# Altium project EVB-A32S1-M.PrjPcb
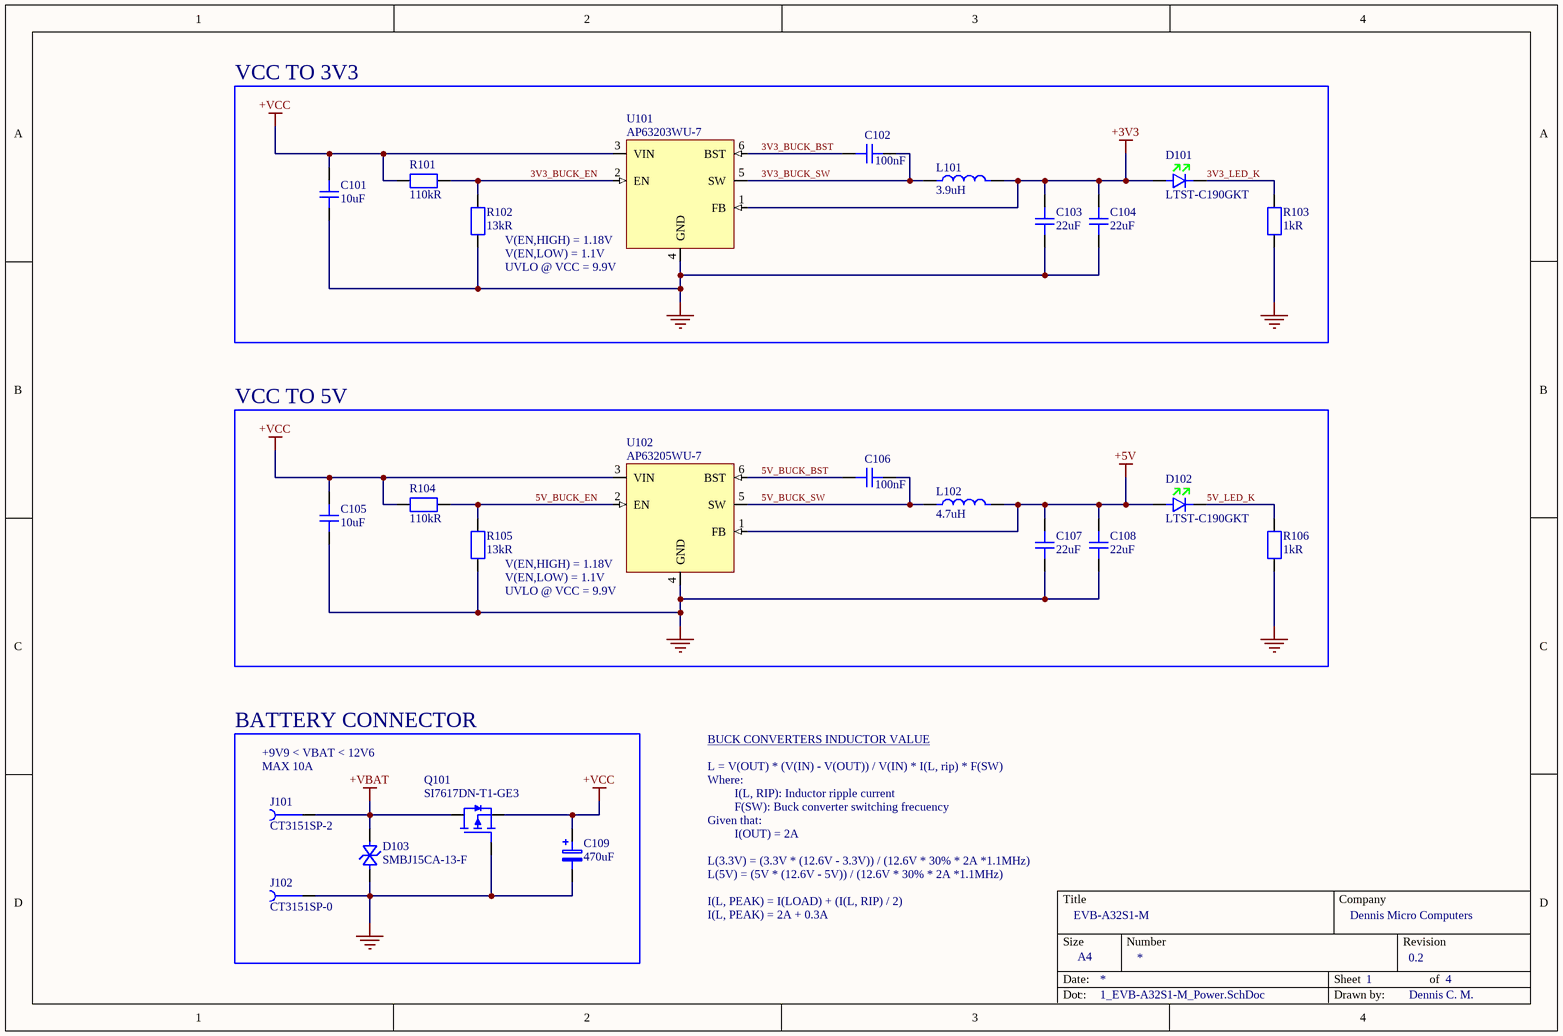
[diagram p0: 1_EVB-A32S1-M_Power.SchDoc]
CompanyName: Dennis Micro Computers; DrawnBy: Dennis C. M.; Revision: 0.2; Title: EVB-A32S1-M
4 sheets, 111 parts. Net scope: flat (ports and power ports of the same name join across sheets).
Board file: EVB-A32S1-M_PCB.PcbDoc
Sheets:
  1_EVB-A32S1-M_Power.SchDoc
  2_EVB-A32S1-M_MCU.SchDoc
  3_EVB-A32S1-M_Motor.SchDoc
  4_EVB-A32S1-M_Sensing.SchDoc

## Sheet 1_EVB-A32S1-M_Power.SchDoc: EVB-A32S1-M
size A4; SheetNumber: 1; SheetTotal: 4

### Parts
C101  value 10uF  [C_Samsung_CL_0805_A]  (hidden comment: CL21A106KOQNNNE)
C102  value 100nF  [C_Samsung_CL_0402_A]  (hidden comment: CL05B104KP5NNNC)
C103  value 22uF  [C_Yageo_CC_0805_A]  (hidden comment: CC0805MKX5R6BB226)
C104  value 22uF  [C_Yageo_CC_0805_A]  (hidden comment: CC0805MKX5R6BB226)
C105  value 10uF  [C_Samsung_CL_0805_A]  (hidden comment: CL21A106KOQNNNE)
C106  value 100nF  [C_Samsung_CL_0402_A]  (hidden comment: CL05B104KP5NNNC)
C107  value 22uF  [C_Yageo_CC_0805_A]  (hidden comment: CC0805MKX5R6BB226)
C108  value 22uF  [C_Yageo_CC_0805_A]  (hidden comment: CC0805MKX5R6BB226)
C109  value 470uF  [C_Rubycon_10x16mm_TH]  (hidden comment: 35ZLH470MEFC10X16)
D101  LTST-C190GKT  [D_LED_Lite-On_Green_0603_A]
D102  LTST-C190GKT  [D_LED_Lite-On_Green_0603_A]
D103  SMBJ15CA-13-F  [D_TVS_BI_Diodes_SMBJ15CA-13-F_A]
J101  CT3151SP-2  [J_CalTest_CT3151SP-2]
J102  CT3151SP-0  [J_CalTest_CT3151SP-0]
L101  value 3.9uH  [L_Murata_1255AY-XXXX=P3]  (hidden comment: 1255AY-3R9N=P3)
L102  value 4.7uH  [L_Murata_1255AY-XXXX=P3]  (hidden comment: 1255AY-4R7M=P3)
Q101  SI7617DN-T1-GE3  [Q_Vishay_PowerPACK-1212-8]
R101  value 110kR  [R_Yageo_RCL_0402_A]  (hidden comment: RC0402FR-07110KL)
R102  value 13kR  [R_Yageo_RCL_0402_A]  (hidden comment: RC0402FR-0713KL)
R103  value 1kR  [R_Yageo_RCL_0402_A]  (hidden comment: RC0402FR-071KL)
R104  value 110kR  [R_Yageo_RCL_0402_A]  (hidden comment: RC0402FR-07110KL)
R105  value 13kR  [R_Yageo_RCL_0402_A]  (hidden comment: RC0402FR-0713KL)
R106  value 1kR  [R_Yageo_RCL_0402_A]  (hidden comment: RC0402FR-071KL)
U101  AP63203WU-7  [U_Diodes_AP623xx]
U102  AP63205WU-7  [U_Diodes_AP623xx]

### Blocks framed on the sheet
VCC TO 3V3: C101-C104 D101 L101 R101-R103 U101
VCC TO 5V: C105-C108 D102 L102 R104-R106 U102
BATTERY CONNECTOR: C109 D103 J101 J102 Q101

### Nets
+3V3: C103.2 C104.2 D101.2 L101.2 U101.1(FB)
+5V: C107.2 C108.2 D102.2 L102.2 U102.1(FB)
+VBAT: D103.1 J101.1 Q101.1(D)
+VCC: C101.2 C105.2 C109.1 Q101.3(S) R101.2 R104.2 U101.3(VIN) U102.3(VIN)
GND: C101.1 C103.1 C104.1 C105.1 C107.1 C108.1 C109.2 D103.2 J102.1 Q101.2(G) R102.1 R103.1 R105.1 R106.1 U101.4(GND) U102.4(GND)
3V3_BUCK_BST: C102.2 U101.6(BST)
3V3_BUCK_EN: R101.1 R102.2 U101.2(EN)
3V3_BUCK_SW: C102.1 L101.1 U101.5(SW)
3V3_LED_K: D101.1 R103.2
5V_BUCK_BST: C106.2 U102.6(BST)
5V_BUCK_EN: R104.1 R105.2 U102.2(EN)
5V_BUCK_SW: C106.1 L102.1 U102.5(SW)
5V_LED_K: D102.1 R106.2

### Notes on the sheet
- (near U101) V(EN,HIGH) = 1.18V
- V(EN,LOW) = 1.1V
- (near U101) UVLO @ VCC = 9.9V
- (near U102) V(EN,HIGH) = 1.18V
- (near U102) UVLO @ VCC = 9.9V
- +9V9 < VBAT < 12V6
- (near J101) MAX 10A
- L = V(OUT) * (V(IN) - V(OUT)) / V(IN) * I(L, rip) * F(SW)
- BUCK CONVERTERS INDUCTOR VALUE
- Where:
- Given that:
- I(L, RIP): Inductor ripple current
- F(SW): Buck converter switching frecuency
- I(OUT) = 2A
- L(3.3V) = (3.3V * (12.6V - 3.3V)) / (12.6V * 30% * 2A *1.1MHz)
- L(5V) = (5V * (12.6V - 5V)) / (12.6V * 30% * 2A *1.1MHz)
- I(L, PEAK) = I(LOAD) + (I(L, RIP) / 2)
- I(L, PEAK) = 2A + 0.3A

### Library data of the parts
C101 C105 = CMP-001-00022-4: Multilayer Ceramic Capacitor, 10 uF, 16 V, ± 10%, X5R, 0805 [2012 Metric]; Voltage Rating (DC): 16V; Dielectric: X7R
C102 C106 = CMP-001-00023-3: Multilayer Ceramic Capacitor, 0.1 uF, 10 V, ± 10%, X7R, 0402 [1005 Metric]; Voltage Rating: 10V
C103 C104 C107 C108 = CMP-001-00014-8: Multilayer Ceramic Capacitor, 22 uF, 10 V, ± 20%, X5R, 0805 [2012 Metric]; Voltage Rating (DC): 10V
C109 = CMP-001-00025-5: Cap Aluminum 470uF 35V 20% (10 X 16mm) Radial 5mm 1760mA 10000h 105 C Bulk; Life (Hours): 10000Hour; Lead Diameter: 0.6mm; Leakage Current: 3uA; Dielectric Material: Aluminium; Ripple Current: 1.76A; Impedance: 28mR
D101 D102 = CMP-007-00001-3: LED Uni-Color Green 565nm 2-Pin Chip LED T/R; Forward Current: 30mA; Forward Voltage: 2.1V; Luminous Intensity: 6mcd; Lens Transparency: Clear; Power Dissipation: 100mW; Lens Style: Flat,Diffused,Colorless,Rectangular,Clear; Lens Size: 0.8mm; Reverse Voltage: 5V; Viewing Angle: 130°; Test Current: 10mA; Dominant Wavelength: 569nm; Lens Color: Colorless; Number of Elements: 1; Voltage: 2V
D103 = CMP-004-00000-11: Tvs Diode, Bidir, 15V, 600W, Do-214Aa Rohs Compliant: Yes; Max Reverse Leakage Current: 5uA; Reverse Breakdown Voltage: 16.7V; Breakdown Voltage: 19.2V; Clamping Voltage: 24.4V; Power Line Protection: No; Max Surge Current: 24A; Number of Bidirectional Channels: 1; Test Current: 1mA; Value: 280pF; Polarity: Bidirectional; Diode Type: ZENER
J101 = CMP-002-00001-14: Conn 4mm Safety Banana Jack F 1 POS Solder RA Thru-Hole 1 Port Bag; pin to pad: 1>1+2+3+4; Body Material: Nylon,Polyamide,PA66; Insulation: Mating End Insulated; Gender: Female
J102 = CMP-002-00000-17: Conn 4mm Safety Banana Jack F 1 POS Solder RA Thru-Hole 1 Port Bag; pin to pad: 1>1+2+3+4; Body Material: Nylon,Polyamide,PA66; Insulation: Mating End Insulated; Gender: Female
L101 = CMP-006-00002-7: Inductor Power Shielded Wirewound 3.9uH 30% 100KHz Ferrite 4.2A 0.0264Ohm DCR 2424 T/R; DC Resistance (DCR): 26.4mR; Saturation Current: 4.7A
L102 = CMP-006-00001-10: Inductor Power Shielded Wirewound 4.7uH 20% 100KHz Ferrite 4A 0.0276Ohm DCR 2424 T/R; DC Resistance (DCR): 27.6mR; Current Rating: 4.5A
Q101 = CMP-00000-19: P CHANNEL MOSFET, -30V, 35A; Transistor; Transistor Polarity: P Channel; Continuous Drain Current Id: -35A; Source; pin to pad: 1>5+6+7+8 2>4 3>1+2+3; Rise Time: 43ns; Drain to Source Resistance: 12.3mR; Turn-Off Delay Time: 30ns; Turn-On Delay Time: 40ns; Threshold Voltage: -2.5V; Max Power Dissipation: 52W; Fall Time: 11ns; Power Dissipation: 3.7W; Polarity: P-CHANNEL; Number of Elements: 1; Input Capacitance: 1.8nF; Gate to Source Voltage (Vgs): 25V
R101 R104 = CMP-009-00000-11: SMD Chip Resistor, 110 kOhm, ± 1%, 63 mW, 0402 [1005 Metric], Thick Film, General Purpose; Max Power Dissipation: 63mW; Voltage Rating (DC): 50V; Temperature Coefficient: 100ppm/°C
R102 R105 = CMP-009-00001-11: SMD Chip Resistor, 13 kOhm, ± 1%, 63 mW, 0402 [1005 Metric], Thick Film, General Purpose; Temperature Coefficient: 100ppm/°C; Voltage Rating: 50V; Max Power Dissipation: 63mW; Power Rating: 62.5mW
R103 R106 = CMP-009-00002-11: SMD Chip Resistor, 1 kOhm, ± 1%, 62.5 mW, 0402 [1005 Metric], Thick Film, General Purpose; Temperature Coefficient: 100ppm/°C; Voltage Rating (AC): 50V; Power Rating: 62.5mW; Max Power Dissipation: 63mW
U101 = CMP-019-00004-17: AP63203 Series 3.3 V 2 A SMT Fixed Low IQ Synchronous Buck - TSOT-26; Max Duty Cycle: 100%; Output Voltage: 3.3V; Number of Outputs: 1; Max Supply Voltage: 32V; Switching Frequency: 1.1MHz; Min Supply Voltage: 3.8V; Nominal Supply Current: 22uA; Output Current: 2A
U102 = CMP-019-00003-17: AP63205 Series 32 V 2 A 1.1 MHz Synchronous Buck Converter -TSOT-26; Number of Outputs: 1; Max Duty Cycle: 100%; Output Current: 2A; Switching Frequency: 1.1MHz; Max Supply Voltage: 32V; Output Voltage: 5V; Nominal Supply Current: 22uA; Min Supply Voltage: 3.8V

## Sheet 2_EVB-A32S1-M_MCU.SchDoc: EVB-A32S1-M
size A4; SheetNumber: 2; SheetTotal: 4
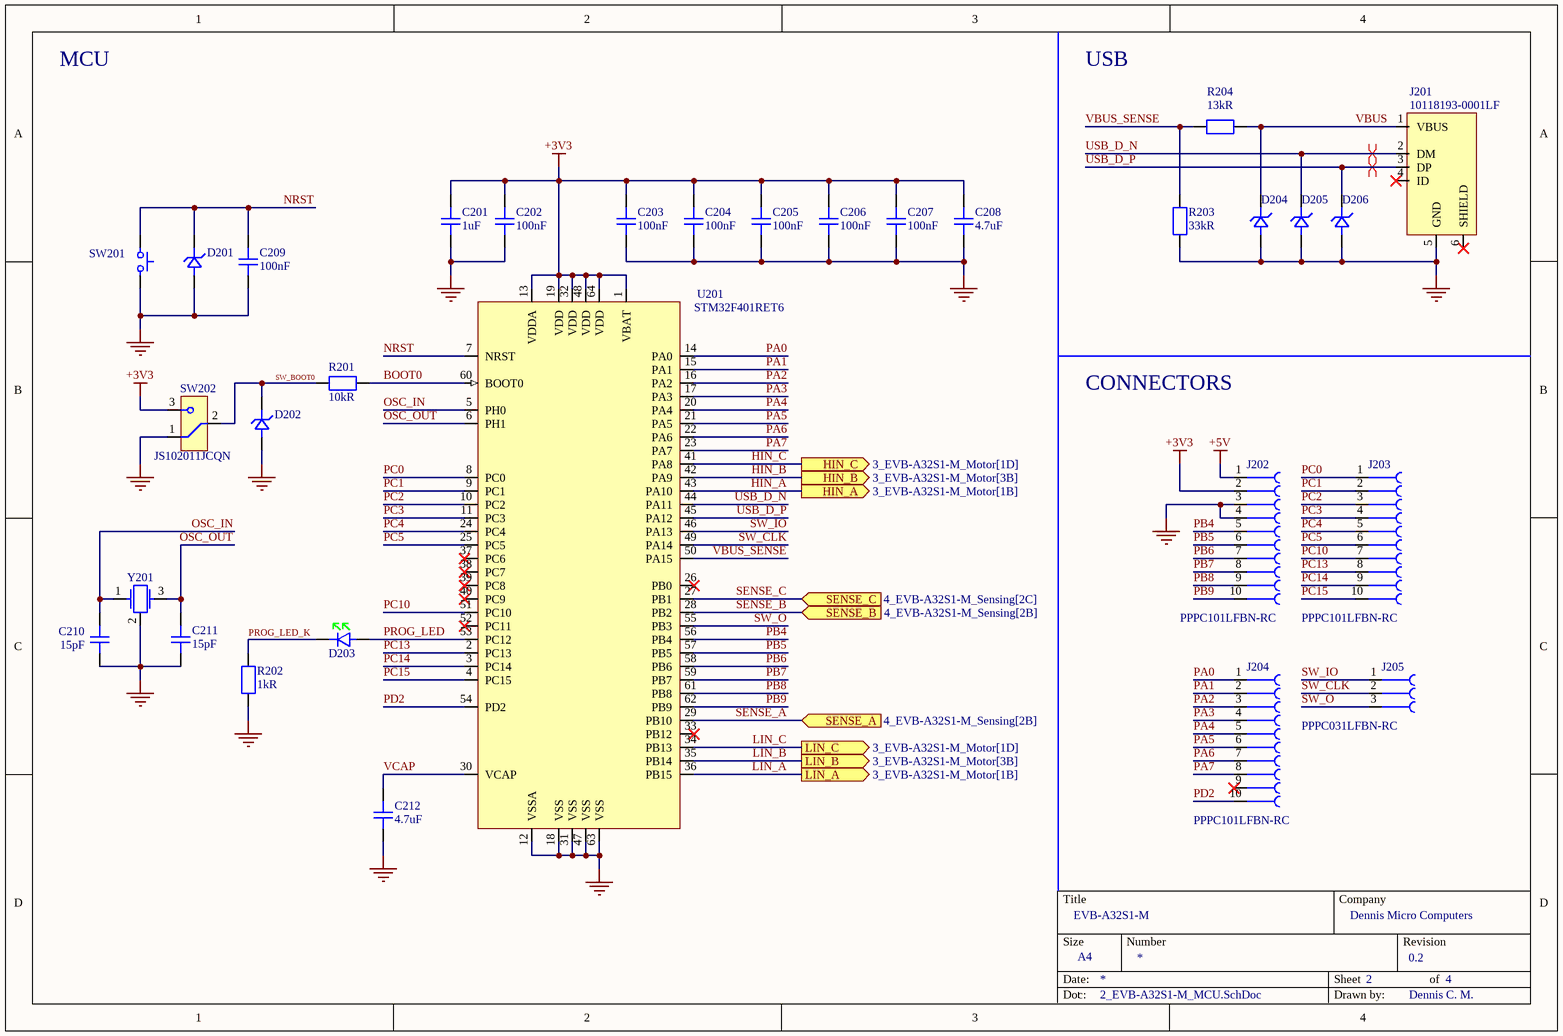
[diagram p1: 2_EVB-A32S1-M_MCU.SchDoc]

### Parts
C201  value 1uF  [C_Yageo_CC_0603_A]  (hidden comment: CC0603KRX7R7BB105)
C202  value 100nF  [C_Samsung_CL_0402_A]  (hidden comment: CL05B104KP5NNNC)
C203  value 100nF  [C_Samsung_CL_0402_A]  (hidden comment: CL05B104KP5NNNC)
C204  value 100nF  [C_Samsung_CL_0402_A]  (hidden comment: CL05B104KP5NNNC)
C205  value 100nF  [C_Samsung_CL_0402_A]  (hidden comment: CL05B104KP5NNNC)
C206  value 100nF  [C_Samsung_CL_0402_A]  (hidden comment: CL05B104KP5NNNC)
C207  value 100nF  [C_Samsung_CL_0402_A]  (hidden comment: CL05B104KP5NNNC)
C208  value 4.7uF  [C_Samsung_CL_0402_A]  (hidden comment: CL05A475MP5NRNC)
C209  value 100nF  [C_Samsung_CL_0402_A]  (hidden comment: CL05B104KP5NNNC)
C210  value 15pF  [C_Yageo_CC_0402_A]  (hidden comment: CC0402JRNPO9BN150)
C211  value 15pF  [C_Yageo_CC_0402_A]  (hidden comment: CC0402JRNPO9BN150)
C212  value 4.7uF  [C_Samsung_CL_0402_A]  (hidden comment: CL05A475MP5NRNC)
D201  D5V0F1U2S9-7  [D_TVS_Uni_Diodes_SOD-923_B]  (value not drawn)
D202  D5V0F1U2S9-7  [D_TVS_Uni_Diodes_SOD-923_B]  (value not drawn)
D203  LTST-C190GKT  [D_LED_Lite-On_Green_0603_A]  (value not drawn)
D204  D5V0F1U2S9-7  [D_TVS_Uni_Diodes_SOD-923_B]  (value not drawn)
D205  D5V0F1U2S9-7  [D_TVS_Uni_Diodes_SOD-923_B]  (value not drawn)
D206  D5V0F1U2S9-7  [D_TVS_Uni_Diodes_SOD-923_B]  (value not drawn)
J201  10118193-0001LF  [J_USB_Micro-B_Amphenol_10118193-0001LF]
J202  PPPC101LFBN-RC  [J_Sullins_01x07_Socket_2.54mm]
J203  PPPC101LFBN-RC  [J_Sullins_01x07_Socket_2.54mm]
J204  PPPC101LFBN-RC  [J_Sullins_01x07_Socket_2.54mm]
J205  PPPC031LFBN-RC  [J_Sullins_01x03_Socket_2.54mm]
R201  value 10kR  [R_Yageo_RCL_0402_A]  (hidden comment: RC0402FR-0710KL)
R202  value 1kR  [R_Yageo_RCL_0402_A]  (hidden comment: RC0402FR-071KL)
R203  value 33kR  [R_Yageo_RCL_0402_A]  (hidden comment: RC0402FR-0733KL)
R204  value 13kR  [R_Yageo_RCL_0402_A]  (hidden comment: RC0402FR-0713KL)
SW201  PTS647SN50SMTR2LFS  [SW_Tactitle_SPST_C&K_PTS647SN50SMTR2LFS]  (value not drawn)
SW202  JS102011JCQN  [SW_Slide_C&K_JS102011JCQN]
U201  STM32F401RET6  [U_ST_STM32F401xD/xE_B]
Y201  ECS-240-12-37B-CKY-TR  [Y_Crystal_GND24_ECS_240-12-37B-CKY-TR]  (value not drawn)

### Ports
HIN_A (out, see 3_EVB-A32S1-M_Motor[1B]), HIN_B (out, see 3_EVB-A32S1-M_Motor[3B]), HIN_C (out, see 3_EVB-A32S1-M_Motor[1D]), LIN_A (out, see 3_EVB-A32S1-M_Motor[1B]), LIN_B (out, see 3_EVB-A32S1-M_Motor[3B]), LIN_C (out, see 3_EVB-A32S1-M_Motor[1D]), SENSE_A (in, see 4_EVB-A32S1-M_Sensing[2B]), SENSE_B (in, see 4_EVB-A32S1-M_Sensing[2B]), SENSE_C (in, see 4_EVB-A32S1-M_Sensing[2C])

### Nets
+3V3: C201.2 C202.2 C203.2 C204.2 C205.2 C206.2 C207.2 C208.2 J202.2 SW202.3 U201.1(VBAT) U201.13(VDDA) U201.19(VDD) U201.32(VDD) U201.48(VDD) U201.64(VDD)
+5V: J202.1
GND: C201.1 C202.1 C203.1 C204.1 C205.1 C206.1 C207.1 C208.1 C209.1 C210.1 C211.1 C212.1 D201.2 D202.2 D204.2 D205.2 D206.2 J201.5(GND) J202.3 J202.4 R202.1 R203.1 SW201.2 SW202.1 U201.12(VSSA) U201.18(VSS) U201.31(VSS) U201.47(VSS) U201.63(VSS) Y201.2
BOOT0: R201.2 U201.60(BOOT0)
HIN_A: U201.43(PA10) ; port HIN_A
HIN_B: U201.42(PA9) ; port HIN_B
HIN_C: U201.41(PA8) ; port HIN_C
LIN_A: U201.36(PB15) ; port LIN_A
LIN_B: U201.35(PB14) ; port LIN_B
LIN_C: U201.34(PB13) ; port LIN_C
NRST: C209.2 D201.1 SW201.1 U201.7(NRST)
OSC_IN: C210.2 U201.5(PH0) Y201.1
OSC_OUT: C211.2 U201.6(PH1) Y201.3
PA0: J204.1 U201.14(PA0)
PA1: J204.2 U201.15(PA1)
PA2: J204.3 U201.16(PA2)
PA3: J204.4 U201.17(PA3)
PA4: J204.5 U201.20(PA4)
PA5: J204.6 U201.21(PA5)
PA6: J204.7 U201.22(PA6)
PA7: J204.8 U201.23(PA7)
PB4: J202.5 U201.56(PB4)
PB5: J202.6 U201.57(PB5)
PB6: J202.7 U201.58(PB6)
PB7: J202.8 U201.59(PB7)
PB8: J202.9 U201.61(PB8)
PB9: J202.10 U201.62(PB9)
PC0: J203.1 U201.8(PC0)
PC1: J203.2 U201.9(PC1)
PC2: J203.3 U201.10(PC2)
PC3: J203.4 U201.11(PC3)
PC4: J203.5 U201.24(PC4)
PC5: J203.6 U201.25(PC5)
PC10: J203.7 U201.51(PC10)
PC13: J203.8 U201.2(PC13)
PC14: J203.9 U201.3(PC14)
PC15: J203.10 U201.4(PC15)
PD2: J204.10 U201.54(PD2)
PROG_LED: D203.2 U201.53(PC12)
PROG_LED_K: D203.1 R202.2
SENSE_A: U201.29(PB10) ; port SENSE_A
SENSE_B: U201.28(PB2) ; port SENSE_B
SENSE_C: U201.27(PB1) ; port SENSE_C
SW_BOOT0: D202.1 R201.1 SW202.2
SW_CLK: J205.2 U201.49(PA14)
SW_IO: J205.1 U201.46(PA13)
SW_O: J205.3 U201.55(PB3)
USB_D_N: D205.1 J201.2(DM) U201.44(PA11)
USB_D_P: D206.1 J201.3(DP) U201.45(PA12)
VBUS: D204.1 J201.1(VBUS) R204.2
VBUS_SENSE: R203.2 R204.1 U201.50(PA15)
VCAP: C212.2 U201.30(VCAP)

Not connected (* = marked no-connect by the designer): J201 4(ID)* 6(SHIELD)*; J204 9*; U201 26(PB0)* 33(PB12)* 37(PC6)* 38(PC7)* 39(PC8)* 40(PC9)* 52(PC11)*

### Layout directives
differential pair; differential pair class DIFF_USB: USB_D_N, USB_D_P

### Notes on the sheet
- MCU
- USB
- CONNECTORS

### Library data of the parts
C201 = CMP-001-00019-4: Multilayer Ceramic Capacitor, 1 uF, 16 V, ± 10%, X7R, 0603 [1608 Metric]; Voltage: 16V; Dissipation Factor: 5%
C202-C207 C209 = CMP-001-00023-3: as C102 on sheet 1_EVB-A32S1-M_Power
C208 C212 = CMP-001-00024-3: Multilayer Ceramic Capacitor, 4.7 uF, 10 V, ± 20%, X5R, 0402 [1005 Metric]; Voltage Rating: 10V
C210 C211 = CMP-001-00017-13: Multilayer Ceramic Capacitor, 15 pF, 10 V, ± 5%, X7R, 0402 [1005 Metric]; Insulation Resistance: 100GR; Dielectric: C0G; Voltage Rating (DC): 50V; Temperature Coefficient: 30ppm/°C
D201 D202 D204-D206 = CMP-004-00003-4: Diode TVS Dual Uni-Dir 5.5V 250000W 2-Pin SOD-923 T/R; Max Power Dissipation: 250mW; ESD Protection: Yes; Max Reverse Leakage Current: 100nA; Capacitance: 0.5pF @ 1MHz; Max Surge Current: 1.5A; Diode Type: ZENER; Direction: Unidirectional; Breakdown Voltage: 6V; Clamping Voltage: 10V; Value: 5E-13F; Peak Pulse Power: 250kW; Number of Unidirectional Channels: 1
D203 = CMP-007-00001-3: LED Uni-Color Green 565nm 2-Pin Chip LED T/R; Viewing Angle: 130°; Lens Transparency: Clear; Reverse Voltage: 5V; Lens Size: 0.8mm; Lens Color: Colorless; Lens Style: Flat,Diffused,Colorless,Rectangular,Clear; Power Dissipation: 100mW; Forward Voltage: 2.1V; Dominant Wavelength: 569nm; Test Current: 10mA; Forward Current: 30mA; Luminous Intensity: 6mcd; Number of Elements: 1; Voltage: 2V
J201 = CMP-002-00002-10: Usb Connector, 5 Contact(S), Female, Right Angle, Surface Mount Terminal, Locking, Receptacle; Number of Contacts: 5; Current Rating: 1.8A; Connector Type: USB,Receptacle; Pitch: 650um; Number of Ports: 1; Voltage Rating: 100V; USB Standard: USB 2.0; Insulation Resistance: 1GR
J202-J204 = CMP-002-00003-7: 10 Position Total Single Row 2.54 mm Pitch Straight Female Header; Voltage Rating: 250V; Number of Contacts: 10; Pitch: 0.1inch; Current Rating: 3A
J205 = CMP-002-00004-7: 3 Position Total Single Row 2.54 mm Pitch Straight Female Header; Voltage Rating: 250V; Number of Positions: 3; Pitch: 2.54mm
R201 = CMP-009-00003-11: SMD Chip Resistor, 10 kOhm, ± 1%, 62.5 mW, 0402 [1005 Metric], Thick Film, General Purpose; Power Rating: 62.5mW; Max Power Dissipation: 63mW; Temperature Coefficient: 100ppm/°C; Voltage Rating (DC): 50V
R202 = CMP-009-00002-11: SMD Chip Resistor, 1 kOhm, ± 1%, 62.5 mW, 0402 [1005 Metric], Thick Film, General Purpose; Temperature Coefficient: 100ppm/°C; Max Power Dissipation: 63mW; Voltage Rating (AC): 50V; Power Rating: 62.5mW
R203 = CMP-009-00005-12: SMD Chip Resistor, 33 kOhm, ± 1%, 63 mW, 0402 [1005 Metric], Thick Film, General Purpose; Power Rating: 63mW; Temperature Coefficient: 100ppm/°C; Voltage Rating (AC): 50V
R204 = CMP-009-00001-11: SMD Chip Resistor, 13 kOhm, ± 1%, 63 mW, 0402 [1005 Metric], Thick Film, General Purpose; Voltage Rating (DC): 50V; Temperature Coefficient: 100ppm/°C; Max Power Dissipation: 63mW; Power Rating: 62.5mW
SW201 = CMP-011-00000-13: Switch Tactile N.O. SPST Round Button Gull Wing 0.05A 12VDC 100000Cycles 0.98N SMD T/R; pin to pad: 1>1+2 2>3+4; Ratings: IP40; Switch Function: Off-Mom; Illumination Type: Non-Illuminated; Actuator Type: Standard; Number of Positions: 2; Operating Force: 100gf; Switch Travel: 0.25mm
SW202 = CMP-011-00001-10: JS Series Sub-Miniature Slide Switch SPDT On-On Top Slide 0.3A 6VDC J-Lead Surface Mount T/R; Voltage Rating (DC): 6V; Switch Travel: 2mm; Actuator Material: Nylon,Polyamide,PA46; Electrical Life: 5000Cycles; Actuator Type: Standard
U201 = CMP-020-00000-10: MCU 32-bit STM32 ARM Cortex M4 RISC 512KB Flash 1.8V/2.5V/3.3V 64-Pin LQFP Tray; Operating Supply Voltage: 3.3V; Peripherals: Brown-out Detect/Reset,POR,PWM,WDT,DMA; Nominal Supply Current: 1.8uA; Number of ADC Channels: 12; Interface: I2C,SPI,USB,IrDA,SDIO,UART,USART,LIN,I2S; Clock Frequency: 84MHz; Number of USB Channels: 1; Number of Timers/Counters: 8; Number of Channels: 16; Number of PWM Channels: 23; Number of UART Channels: 3; Number of Programmable I/O: 50; Watchdog Timer: Yes; Max Power Dissipation: 313mW; Min Supply Voltage: 1.7V; Data Bus Width: 32b; RAM Size: 96KB; Max Supply Voltage: 3.6V; Oscillator Type: Internal
Y201 = CMP-003-00000-10: Crystal 24MHz ±10ppm (Tol) ±10ppm (Stability) 12pF FUND 50Ohm 4-Pin Mini-CSMD T/R; pin to pad: 2>2+4

## Sheet 3_EVB-A32S1-M_Motor.SchDoc: EVB-A32S1-M
size A4; SheetNumber: 3; SheetTotal: 4
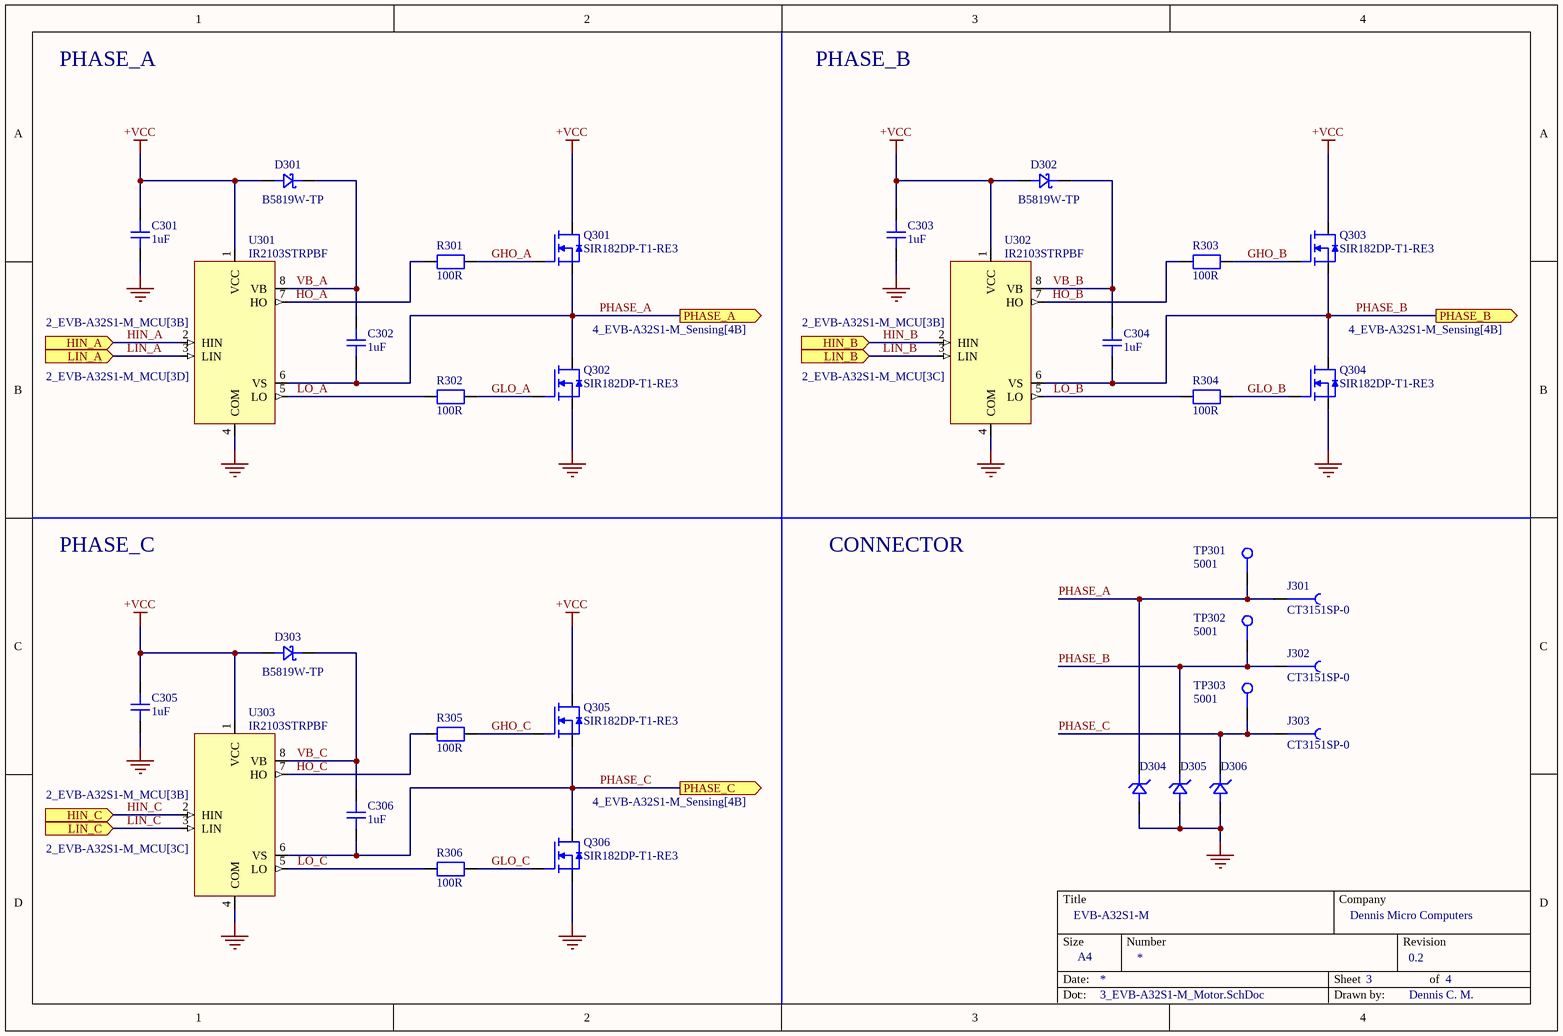
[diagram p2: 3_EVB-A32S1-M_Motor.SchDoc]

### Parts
C301  value 1uF  [C_Yageo_CC_0603_A]  (hidden comment: CC0603KRX7R7BB105)
C302  value 1uF  [C_Yageo_CC_0603_A]  (hidden comment: CC0603KRX7R7BB105)
C303  value 1uF  [C_Yageo_CC_0603_A]  (hidden comment: CC0603KRX7R7BB105)
C304  value 1uF  [C_Yageo_CC_0603_A]  (hidden comment: CC0603KRX7R7BB105)
C305  value 1uF  [C_Yageo_CC_0603_A]  (hidden comment: CC0603KRX7R7BB105)
C306  value 1uF  [C_Yageo_CC_0603_A]  (hidden comment: CC0603KRX7R7BB105)
D301  B5819W-TP  [D_Schottky_MCC_SOD-123]
D302  B5819W-TP  [D_Schottky_MCC_SOD-123]
D303  B5819W-TP  [D_Schottky_MCC_SOD-123]
D304  SMBJ15A-13-F  [D_TVS_Uni_Diodes_DO-214AA_B]  (value not drawn)
D305  SMBJ15A-13-F  [D_TVS_Uni_Diodes_DO-214AA_B]  (value not drawn)
D306  SMBJ15A-13-F  [D_TVS_Uni_Diodes_DO-214AA_B]  (value not drawn)
J301  CT3151SP-0  [J_CalTest_CT3151SP-0]
J302  CT3151SP-0  [J_CalTest_CT3151SP-0]
J303  CT3151SP-0  [J_CalTest_CT3151SP-0]
Q301  SIR182DP-T1-RE3  [Q_Vishay_PowerPACK-SO-8-Single]
Q302  SIR182DP-T1-RE3  [Q_Vishay_PowerPACK-SO-8-Single]
Q303  SIR182DP-T1-RE3  [Q_Vishay_PowerPACK-SO-8-Single]
Q304  SIR182DP-T1-RE3  [Q_Vishay_PowerPACK-SO-8-Single]
Q305  SIR182DP-T1-RE3  [Q_Vishay_PowerPACK-SO-8-Single]
Q306  SIR182DP-T1-RE3  [Q_Vishay_PowerPACK-SO-8-Single]
R301  value 100R  [R_Yageo_RCL_1206_A]  (hidden comment: RC1206FR-07100RL)
R302  value 100R  [R_Yageo_RCL_1206_A]  (hidden comment: RC1206FR-07100RL)
R303  value 100R  [R_Yageo_RCL_1206_A]  (hidden comment: RC1206FR-07100RL)
R304  value 100R  [R_Yageo_RCL_1206_A]  (hidden comment: RC1206FR-07100RL)
R305  value 100R  [R_Yageo_RCL_1206_A]  (hidden comment: RC1206FR-07100RL)
R306  value 100R  [R_Yageo_RCL_1206_A]  (hidden comment: RC1206FR-07100RL)
TP301  5001  [TP_Keystone_TH]
TP302  5001  [TP_Keystone_TH]
TP303  5001  [TP_Keystone_TH]
U301  IR2103STRPBF  [U_Infineon_8-SOIC_3.9mm]
U302  IR2103STRPBF  [U_Infineon_8-SOIC_3.9mm]
U303  IR2103STRPBF  [U_Infineon_8-SOIC_3.9mm]

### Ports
HIN_A (in, see 2_EVB-A32S1-M_MCU[3B]), HIN_B (in, see 2_EVB-A32S1-M_MCU[3B]), HIN_C (in, see 2_EVB-A32S1-M_MCU[3B]), LIN_A (in, see 2_EVB-A32S1-M_MCU[3D]), LIN_B (in, see 2_EVB-A32S1-M_MCU[3C]), LIN_C (in, see 2_EVB-A32S1-M_MCU[3C]), PHASE_A (out, see 4_EVB-A32S1-M_Sensing[4B]), PHASE_B (out, see 4_EVB-A32S1-M_Sensing[4B]), PHASE_C (out, see 4_EVB-A32S1-M_Sensing[4B])

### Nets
+VCC: C301.2 C303.2 C305.2 D301.2 D302.2 D303.2 Q301.1(D) Q303.1(D) Q305.1(D) U301.1(VCC) U302.1(VCC) U303.1(VCC)
GND: C301.1 C303.1 C305.1 D304.2 D305.2 D306.2 Q302.3(S) Q304.3(S) Q306.3(S) U301.4(COM) U302.4(COM) U303.4(COM)
GHO_A: Q301.2(G) R301.2
GHO_B: Q303.2(G) R303.2
GHO_C: Q305.2(G) R305.2
GLO_A: Q302.2(G) R302.2
GLO_B: Q304.2(G) R304.2
GLO_C: Q306.2(G) R306.2
HIN_A: U301.2(HIN) ; port HIN_A
HIN_B: U302.2(HIN) ; port HIN_B
HIN_C: U303.2(HIN) ; port HIN_C
HO_A: R301.1 U301.7(HO)
HO_B: R303.1 U302.7(HO)
HO_C: R305.1 U303.7(HO)
LIN_A: U301.3(LIN) ; port LIN_A
LIN_B: U302.3(LIN) ; port LIN_B
LIN_C: U303.3(LIN) ; port LIN_C
LO_A: R302.1 U301.5(LO)
LO_B: R304.1 U302.5(LO)
LO_C: R306.1 U303.5(LO)
PHASE_A: C302.1 D304.1 J301.1 Q301.3(S) Q302.1(D) TP301.1 U301.6(VS) ; port PHASE_A
PHASE_B: C304.1 D305.1 J302.1 Q303.3(S) Q304.1(D) TP302.1 U302.6(VS) ; port PHASE_B
PHASE_C: C306.1 D306.1 J303.1 Q305.3(S) Q306.1(D) TP303.1 U303.6(VS) ; port PHASE_C
VB_A: C302.2 D301.1 U301.8(VB)
VB_B: C304.2 D302.1 U302.8(VB)
VB_C: C306.2 D303.1 U303.8(VB)

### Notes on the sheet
- PHASE_A
- PHASE_B
- PHASE_C
- CONNECTOR

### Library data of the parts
C301-C306 = CMP-001-00019-4: as C201 on sheet 2_EVB-A32S1-M_MCU
D301-D303 = CMP-000001-2: Rectifier Diode, Schottky, 1 Phase, 1 Element, 1A, 40V V(RRM), Silicon; Max Reverse Voltage (DC): 20V; Max Forward Surge Current (Ifsm): 10A; Forward Voltage: 550mV; Max Reverse Current: 1mA; Max Power Dissipation: 250mW
D304-D306 = CMP-004-00005-2: TVS Diode Single Uni-Dir 15V 600W 2-Pin SMB T/R / TVS DIODE 15VWM 24.4VC SMB; Max Reverse Leakage Current: 5uA; Max Surge Current: 24A; Diode Type: ZENER; Power Line Protection: No; Direction: Unidirectional; Breakdown Voltage: 19.2V; Clamping Voltage: 24.4V; Value: 800pF; Min Breakdown Voltage: 16.7V; Number of Unidirectional Channels: 1; Forward Voltage: 5V; Test Current: 1mA
J301-J303 = CMP-002-00000-17: Conn 4mm Safety Banana Jack F 1 POS Solder RA Thru-Hole 1 Port Bag; pin to pad: 1>1+2+3+4; Gender: Female; Insulation: Mating End Insulated; Body Material: Nylon,Polyamide,PA66
Q301-Q306 = CMP-013-00000-7: TrenchFET Gen IV Power MOSFET N-Channel Single 60V VDS ±20V VGS 60A ID 8-Pin PowerPAK SOIC T/R; pin to pad: 1>5+6+7+8 2>4 3>1+2+3; Rds On Max: 2.8mR; Max Power Dissipation: 69.4W; Input Capacitance: 3.25nF
R301-R306 = CMP-009-00004-12: SMD Chip Resistor, 100 Ohm, ± 1%, 250 mW, 1206 [3216 Metric], Thick Film, General Purpose; Max Power Dissipation: 250mW; Voltage Rating (AC): 200V; Temperature Coefficient: 100ppm/°C
TP301-TP303 = CMP-000000-5: TEST POINT, PCB, THROUGH HOLE; Product R; Range: -; Connector Colour: Black; Mounting: Through Hole; Body Material: Bronze; Insulation: Insulated; Plating: Silver; Number of Ports: 1; Inside Diameter: 1.27mm; Hole Diameter: 1.6mm; Outside Diameter: 2.54mm
U301-U303 = CMP-024-00000-6: 600 V half-bridge gate driver IC with shoot through protection, SOIC 8N, RoHS; Number of Outputs: 2; Max Supply Voltage: 20V; Propagation Delay: 680ns; Fall Time: 60ns; Channel Type: Independent; Output Current: 360mA

## Sheet 4_EVB-A32S1-M_Sensing.SchDoc: EVB-A32S1-M
size A4; Author: Dennis C. M; CompanyName: Dennis Micro Computers; DrawnBy: Dennis C. M.; SheetNumber: 4; SheetTotal: 4; Size: A4
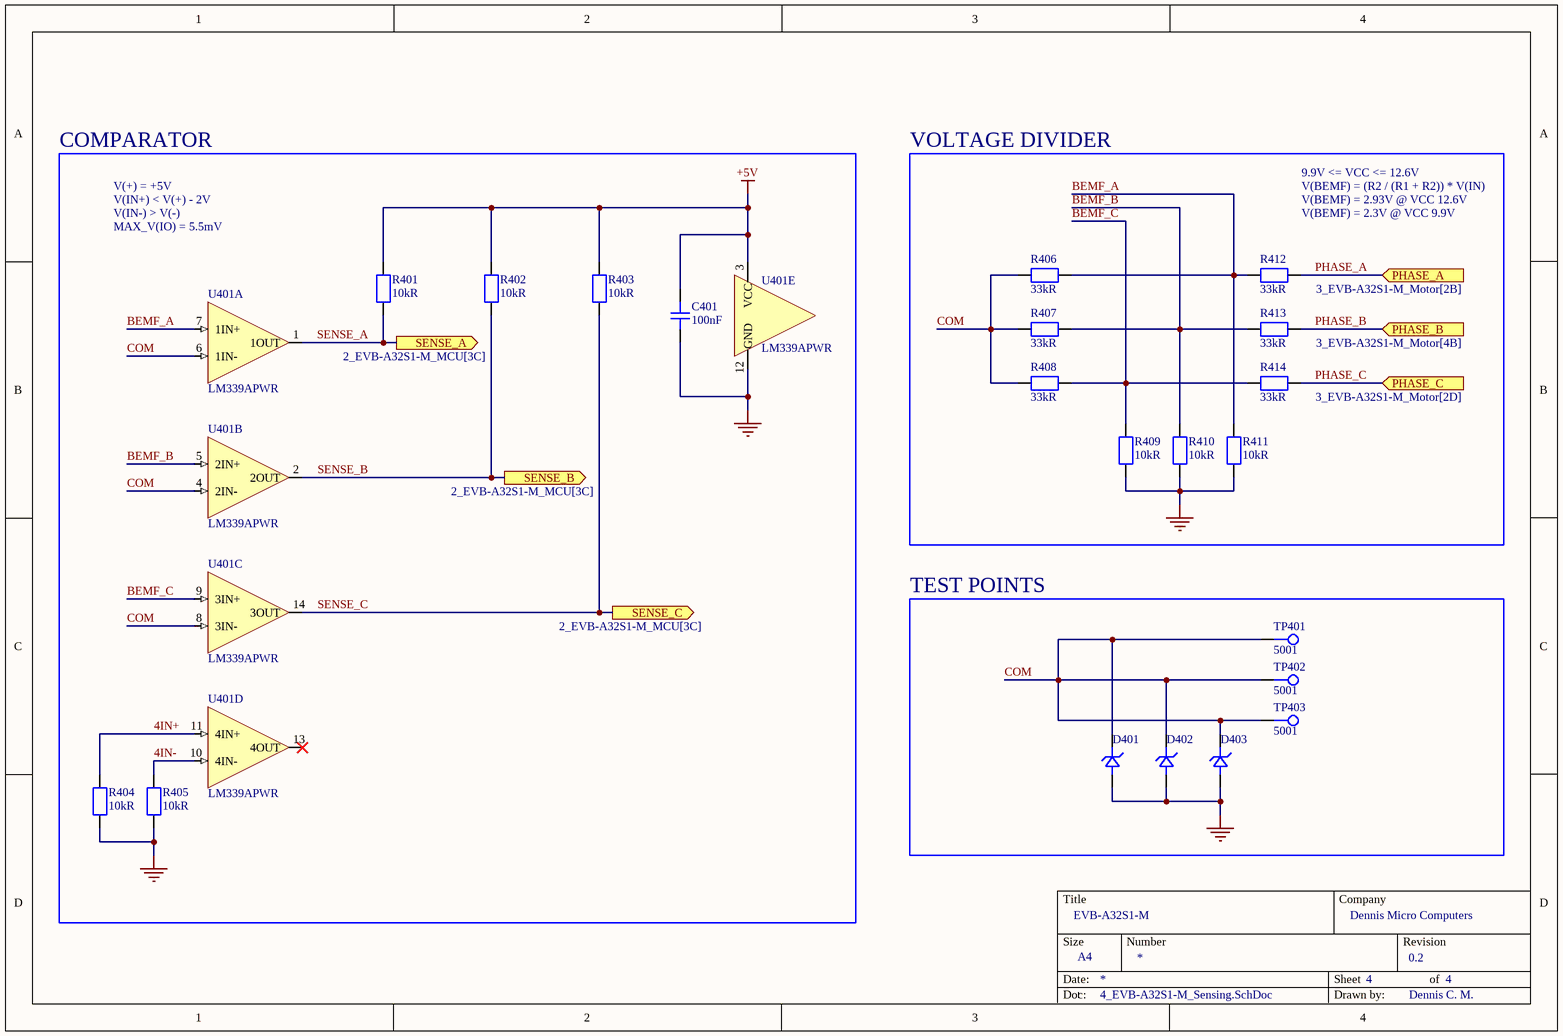
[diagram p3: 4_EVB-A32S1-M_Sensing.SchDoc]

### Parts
C401  value 100nF  [C_Samsung_CL_0402_A]  (hidden comment: CL05B104KP5NNNC)
D401  SMBJ15A-13-F  [D_TVS_Uni_Diodes_DO-214AA_B]  (value not drawn)
D402  SMBJ15A-13-F  [D_TVS_Uni_Diodes_DO-214AA_B]  (value not drawn)
D403  SMBJ15A-13-F  [D_TVS_Uni_Diodes_DO-214AA_B]  (value not drawn)
R401  value 10kR  [R_Yageo_RCL_0402_A]  (hidden comment: RC0402FR-0710KL)
R402  value 10kR  [R_Yageo_RCL_0402_A]  (hidden comment: RC0402FR-0710KL)
R403  value 10kR  [R_Yageo_RCL_0402_A]  (hidden comment: RC0402FR-0710KL)
R404  value 10kR  [R_Yageo_RCL_0402_A]  (hidden comment: RC0402FR-0710KL)
R405  value 10kR  [R_Yageo_RCL_0402_A]  (hidden comment: RC0402FR-0710KL)
R406  value 33kR  [R_Yageo_RCL_0402_A]  (hidden comment: RC0402FR-0733KL)
R407  value 33kR  [R_Yageo_RCL_0402_A]  (hidden comment: RC0402FR-0733KL)
R408  value 33kR  [R_Yageo_RCL_0402_A]  (hidden comment: RC0402FR-0733KL)
R409  value 10kR  [R_Yageo_RCL_0402_A]  (hidden comment: RC0402FR-0710KL)
R410  value 10kR  [R_Yageo_RCL_0402_A]  (hidden comment: RC0402FR-0710KL)
R411  value 10kR  [R_Yageo_RCL_0402_A]  (hidden comment: RC0402FR-0710KL)
R412  value 33kR  [R_Yageo_RCL_0402_A]  (hidden comment: RC0402FR-0733KL)
R413  value 33kR  [R_Yageo_RCL_0402_A]  (hidden comment: RC0402FR-0733KL)
R414  value 33kR  [R_Yageo_RCL_0402_A]  (hidden comment: RC0402FR-0733KL)
TP401  5001  [TP_Keystone_TH]
TP402  5001  [TP_Keystone_TH]
TP403  5001  [TP_Keystone_TH]
U401  LM339APWR  [U_TI_14-TSSOP-5.00x4.40mm_0.62mm_B]  (parts A,B,C,D,E of 5)

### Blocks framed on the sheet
COMPARATOR: C401 R401-R405 U401
VOLTAGE DIVIDER: R406-R414
TEST POINTS: D401-D403 TP401-TP403

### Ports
PHASE_A (in, see 3_EVB-A32S1-M_Motor[2B]), PHASE_B (in, see 3_EVB-A32S1-M_Motor[4B]), PHASE_C (in, see 3_EVB-A32S1-M_Motor[2D]), SENSE_A (out, see 2_EVB-A32S1-M_MCU[3C]), SENSE_B (out, see 2_EVB-A32S1-M_MCU[3C]), SENSE_C (out, see 2_EVB-A32S1-M_MCU[3C])

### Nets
+5V: C401.2 R401.2 R402.2 R403.2 U401.3(VCC)
GND: C401.1 D401.2 D402.2 D403.2 R404.1 R405.1 R409.1 R410.1 R411.1 U401.12(GND)
4IN+: R404.2 U401.11(4IN+)
4IN-: R405.2 U401.10(4IN-)
BEMF_A: R406.2 R411.2 R412.1 U401.7(1IN+)
BEMF_B: R407.2 R410.2 R413.1 U401.5(2IN+)
BEMF_C: R408.2 R409.2 R414.1 U401.9(3IN+)
COM: D401.1 D402.1 D403.1 R406.1 R407.1 R408.1 TP401.1 TP402.1 TP403.1 U401.4(2IN-) U401.6(1IN-) U401.8(3IN-)
PHASE_A: R412.2 ; port PHASE_A
PHASE_B: R413.2 ; port PHASE_B
PHASE_C: R414.2 ; port PHASE_C
SENSE_A: R401.1 U401.1(1OUT) ; port SENSE_A
SENSE_B: R402.1 U401.2(2OUT) ; port SENSE_B
SENSE_C: R403.1 U401.14(3OUT) ; port SENSE_C

Not connected (* = marked no-connect by the designer): U401 13(4OUT)*

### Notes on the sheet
- 9.9V <= VCC <= 12.6V
- V(IN+) < V(+) - 2V
- V(IN-) > V(-)
- MAX_V(IO) = 5.5mV
- V(+) = +5V
- V(BEMF) = (R2 / (R1 + R2)) * V(IN)
- V(BEMF) = 2.93V @ VCC 12.6V
- V(BEMF) = 2.3V @ VCC 9.9V

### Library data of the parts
C401 = CMP-001-00023-3: Multilayer Ceramic Capacitor, 0.1 uF, 10 V, ± 10%, X7R, 0402 [1005 Metric]; Voltage Rating (DC): 10V
D401-D403 = CMP-004-00005-2: as D304 on sheet 3_EVB-A32S1-M_Motor
R401-R405 R409-R411 = CMP-009-00003-11: SMD Chip Resistor, 10 kOhm, ± 1%, 62.5 mW, 0402 [1005 Metric], Thick Film, General Purpose; Power Rating: 62.5mW; Temperature Coefficient: 100ppm/°C; Max Power Dissipation: 63mW; Voltage Rating (DC): 50V
R406-R408 R412-R414 = CMP-009-00005-12: as R203 on sheet 2_EVB-A32S1-M_MCU
TP401-TP403 = CMP-000000-5: as TP301 on sheet 3_EVB-A32S1-M_Motor
U401 = CMP-016-00000-9: Precision quad differential comparator, commercial grade 14-TSSOP 0 to 70; Output Compatibility: CMOS; Supply Current: 2mA; Min Dual Supply Voltage: 1V; Max Dual Supply Voltage: 15V; Max Supply Current: 500uA; Voltage Gain: 106.02dB; Output Current per Channel: 6mA; Input Offset Voltage (Vos): 3mV; Max Input Current: 250nA; Min Supply Voltage: 2V; Number of Channels: 4; Max Supply Voltage: 30V; Output Type: TTL; Response Time: 1.3us; Output Current: 20mA; Quiescent Current: 2.5mA

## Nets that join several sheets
+3V3: 1_EVB-A32S1-M_Power (5 pins), 2_EVB-A32S1-M_MCU (16 pins)
+5V: 1_EVB-A32S1-M_Power (5 pins), 2_EVB-A32S1-M_MCU (J202.1), 4_EVB-A32S1-M_Sensing (5 pins)
+VCC: 1_EVB-A32S1-M_Power (8 pins), 3_EVB-A32S1-M_Motor (12 pins)
GND: 1_EVB-A32S1-M_Power (16 pins), 2_EVB-A32S1-M_MCU (30 pins), 3_EVB-A32S1-M_Motor (12 pins), 4_EVB-A32S1-M_Sensing (10 pins)
HIN_A: 2_EVB-A32S1-M_MCU (U201.43), 3_EVB-A32S1-M_Motor (U301.2)
HIN_B: 2_EVB-A32S1-M_MCU (U201.42), 3_EVB-A32S1-M_Motor (U302.2)
HIN_C: 2_EVB-A32S1-M_MCU (U201.41), 3_EVB-A32S1-M_Motor (U303.2)
LIN_A: 2_EVB-A32S1-M_MCU (U201.36), 3_EVB-A32S1-M_Motor (U301.3)
LIN_B: 2_EVB-A32S1-M_MCU (U201.35), 3_EVB-A32S1-M_Motor (U302.3)
LIN_C: 2_EVB-A32S1-M_MCU (U201.34), 3_EVB-A32S1-M_Motor (U303.3)
PHASE_A: 3_EVB-A32S1-M_Motor (7 pins), 4_EVB-A32S1-M_Sensing (R412.2)
PHASE_B: 3_EVB-A32S1-M_Motor (7 pins), 4_EVB-A32S1-M_Sensing (R413.2)
PHASE_C: 3_EVB-A32S1-M_Motor (7 pins), 4_EVB-A32S1-M_Sensing (R414.2)
SENSE_A: 2_EVB-A32S1-M_MCU (U201.29), 4_EVB-A32S1-M_Sensing (R401.1 U401.1)
SENSE_B: 2_EVB-A32S1-M_MCU (U201.28), 4_EVB-A32S1-M_Sensing (R402.1 U401.2)
SENSE_C: 2_EVB-A32S1-M_MCU (U201.27), 4_EVB-A32S1-M_Sensing (R403.1 U401.14)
